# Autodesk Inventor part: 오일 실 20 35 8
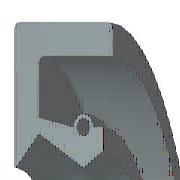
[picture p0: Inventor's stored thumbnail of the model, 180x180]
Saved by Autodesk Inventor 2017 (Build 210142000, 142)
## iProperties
IsCustomPart: 0
Created: 2018-09
Part Number: 오일 실 20 35 8
Material: 고무
Description: 오일-실
Document SubType Name: Modeling
Standard: KS B 2804
Standards Organization: KS
Language: ko-KR
Size Designation: D - 20 35 8
Categories: <MemberInstance><Categories><Category DisplayName="샤프트 부품" InternalName="7f7aeb1f-a693-4053-b835-cee3144e0d98" Mnemonic="SHFT"><Category DisplayName="실링" Intern
Density: 0.93 g/cm^3
Mass: 2.54606 g
Surface Area: 35.9421 cm^2
Volume: 2.7377 cm^3
Appearance: 고무 - 검은색 - 버전 1.1
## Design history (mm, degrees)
revolve "본체" stored, may be unused: angle "d17" = 90 deg
revolve "스프링1" stored, may be unused: angle "d18" = 90 deg
body "Solid1"
sketch "스케치1"
  geometry: L1 (0, 17.5)-(8, 17.5); L2 (8, 15.75)-(1.75, 15.75); L3 (1.75, 11.75)-(4.9, 10); L4 (4.9, 10)-(0, 10); L5 (0, 0)-(9.586, 0) reference; L6 (4.9, 10)-(6.3, 10.875); L7 (0, 18)-(0, -3) reference; L8 (-1.941, 0)-(11.507, 0) reference; L9 (4.2, 12.1)-(1.75, 12.71); L10 (1.75, 12.71)-(1.75, 15.75); L11 (0, 17.5)-(0, 10.088); L12 (4.9, 10)-(0, 10); L13 (1.75, 11.75)-(0.152, 10.028); L14 (8, 17.5)-(8, 15.75); L15 (5.6, 12.1)-(6.3, 12.1); L16 (6.3, 12.1)-(6.3, 10.875); C1 r 0.455 at (4.9, 12.1); A1 r 0.7 centre (4.9, 12.1) between (5.6, 12.1) and (4.2, 12.1); A2 r 0.088 centre (0.088, 10.088) between (0, 10.088) and (0.152, 10.028); 1 further point
  constraints: 28 end point, 5 horizontal alignment, 5 point on line, 4 point on circle, 4 vertical alignment, 3 centre point, 3 tangent, 2 collinear, 2 horizontal, 2 perpendicular, 1 coincident, 1 parallel
  dimensions: "d0" = 35 diameter of L1 L5 (= SD2); "d1" = 1.75 distance of L1.end L2.start (= SD); "d2" = 0.91 diameter of C1 (= SPDI); "d3" = 1.4 diameter of A1 (= SPDA); "d4" = 20 diameter of L3.end L5 (= NND); "d5" = 23.5 diameter of L3.start L5 (= TKDM); "d7" = 25.42 diameter of L9.end L5 (= TKDM + 0.24 x SWDT); "d8" = 1.75 distance between parallel lines of L11 L10 (= SD); "d9" = 4.9 distance from line of L11 C1.centre (= SPDST); "d10" = 24.2 diameter of C1.centre L5 (= HLDM); "d11" = 0.0875 radius of A2 (= 0.25 x LAB); "d12" = 6.3 distance between parallel lines of L11 L16 (= SDI); "d13" = 21.75 diameter of L6.end L5 (= ABDM); "d14" = 8 distance from line of L11 L1.end (= SWDT)
fillet "모깎기1" dims "d6" = 0.3 (= RR)
other parameters: "SD2" = 35 [user parameter; used in 1 equation term], "SWDT" = 8 [user parameter; used in 2 equation terms], "RR" = 0.3 [user parameter; used in 1 equation term], "SD" = 1.75 [user parameter; used in 2 equation terms], "NND" = 20 [user parameter; used in 1 equation term], "SPDA" = 1.4 [user parameter; used in 1 equation term], "SPDI" = 0.91 [user parameter; used in 1 equation term], "TKDM" = 23.5 [user parameter; used in 2 equation terms], "HLDM" = 24.2 [user parameter; used in 1 equation term], "ABDM" = 21.75 [user parameter; used in 1 equation term], "SDI" = 6.3 [user parameter; used in 1 equation term], "SPDST" = 4.9 [user parameter; used in 1 equation term], "LAB" = 0.35 [user parameter; used in 1 equation term], "d15" = 0, "d16" = 0, "d19" = 0
